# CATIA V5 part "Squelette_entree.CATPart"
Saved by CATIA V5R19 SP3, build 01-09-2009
Part number: Squelette_entree
Bounding box of the stored display mesh (mm): x 0 to 0, y -212 to 0, z -76 to 76
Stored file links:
  C:\Users\Frédéric\Documents\WF\STSCPI 09-11\Projets\Projet multiplicateur eolienne\Maquette eolienne\Squelette_entree.CATPart
  C:\Users\Frédéric\Documents\WF\STSCPI 09-11\Projets\Projet multiplicateur eolienne\Maquette eolienne\Squelette_carter.CATPart
  C:\Users\Frédéric\Documents\WF\STSCPI 09-11\Projets\Projet multiplicateur eolienne\Maquette eolienne\Multiplicateur_eolien.CATProduct
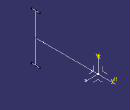
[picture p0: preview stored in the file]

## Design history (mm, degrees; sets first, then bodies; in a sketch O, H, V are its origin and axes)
External parameters (linked from other documents)
  External.Offset = 20 mm
  `External.Ecartement palier arbre 9` = 155 mm
  `External.rayon primitif A et C` = 76 mm
AxisSystem1: origin (0, 0, 0), X (1, 0, 0), Y (0, 1, 0), Z (0, 0, 1)
Body1 (main body)
  Sketch1 on YZ plane of AxisSystem1, origin (0, 0, 0), H (0, 1, 0), V (0, 0, 1)
    point P1 (-200, 0)
    line L1 (-200, 0) -> (-200, 76)
    point P2 (-200, 76)
    line L2 (-200, 76) -> (-212, 76)
    point P3 (-212, 76)
    line L3 (-200, 76) -> (-188, 76)
    point P4 (-188, 76)
    line L4 (0, 0) -> (-20, 0)
    point P5 (-20, 0)
    line L5 (-20, 0) -> (-175, 0)
    point P6 (-175, 0)
    line L6 (-175, 0) -> (-200, 0)
    point P7 (-20, 0)
    point P8 (-175, 0)
    point P9 (-200, 0)
    point P10 (-200, -76)
    point P11 (-212, -76)
    point P12 (-188, -76)
    line L7 (-200, 0) -> (-200, -76)
    line L8 (-200, -76) -> (-212, -76)
    line L9 (-200, -76) -> (-188, -76)
    length L2 = 12
    length L3 = 12 {= Sketch1.length(L2)}
    length L1 = 76 {= `External.rayon primitif A et C`}
    distance V L1 = 200
    length L4 = 20
    length L5 = 155 {= `External.Ecartement palier arbre 9`}
    vertical: L1 V
    horizontal: L2 H, L3 H, L4 H, L5 H, L6 H
    coincidence: P7 P5, P8 P6
    symmetry: P1 P9 L6, P2 P10 L6, P3 P11 L6, P4 P12 L6, L1 L7 L6, L2 L8 L6, L3 L9 L6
